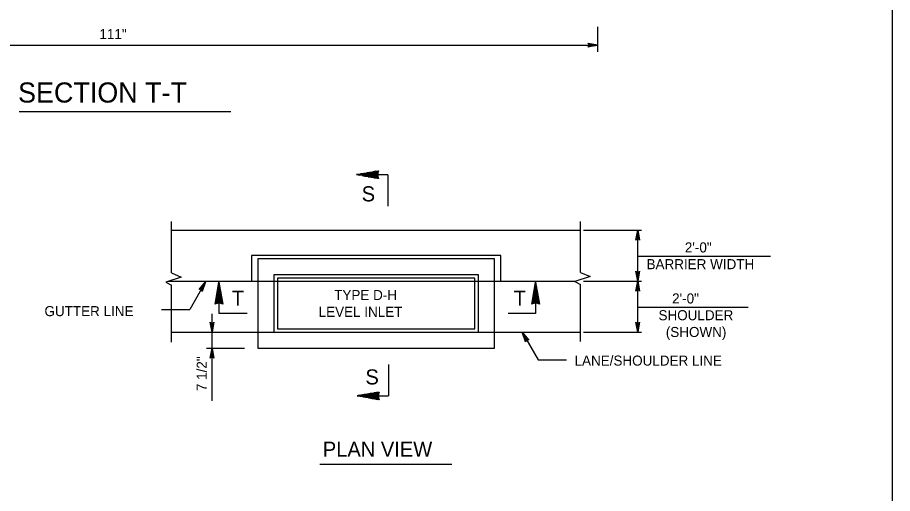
# Model space of a CAD drawing. Extents: x 2087776 to 2104538, y 970919 to 982612.
# Drawn here: x 2095145 to 2096001, y 979635 to 980101 of the extents above; entities that cross this region are included whole.
import ezdxf

# ---------------------------------------------------------------- set-up
doc = ezdxf.new("R2010")
doc.units = 0
doc.layers.add('1', color=7, linetype='Continuous')

msp = doc.modelspace()

# ---------------------------------------------------------------- linework, layer by layer
at = {"layer": '1'}
for p, q in [((2095712.65, 980067.42), (2095712.65, 980091.85)), ((2094787.65, 980073.9), (2095712.65, 980073.9)), ((2095146.59, 980009.06), (2095353.51, 980009.06)), ((2095497.32, 979947.29), (2095507.2, 979947.29)), ((2095507.28, 979947.24), (2095507.28, 979916.58)), ((2095295.77, 979851.22), (2095295.77, 979901.31)), ((2095695.77, 979851.66), (2095695.77, 979901.31)), ((2095295.77, 979893.06), (2095695.77, 979893.06)), ((2095698.46, 979893.06), (2095755.26, 979893.06)), ((2095751.62, 979843.06), (2095751.62, 979893.06)), ((2095617.64, 979868.06), (2095373.89, 979868.06)), ((2095373.89, 979868.06), (2095373.89, 979843.06)), ((2095611.39, 979864.94), (2095380.14, 979864.94)), ((2095380.14, 979864.94), (2095380.14, 979843.06)), ((2095611.39, 979843.06), (2095611.39, 979864.94)), ((2095617.64, 979843.06), (2095617.64, 979868.06)), ((2095751.62, 979867.66), (2095881.41, 979867.66)), ((2095595.77, 979849.31), (2095395.77, 979849.31)), ((2095395.77, 979849.31), (2095395.77, 979843.06)), ((2095592.38, 979845.93), (2095399.15, 979845.93)), ((2095399.15, 979845.93), (2095399.15, 979843.06)), ((2095592.38, 979843.06), (2095592.38, 979845.93)), ((2095595.77, 979843.06), (2095595.77, 979849.31)), ((2095292.75, 979843.06), (2095691.46, 979843.06)), ((2095295.77, 979783.36), (2095295.77, 979839.18)), ((2095329.03, 979842.52), (2095313.53, 979815.44)), ((2095380.14, 979843.06), (2095380.14, 979777.44)), ((2095395.77, 979843.06), (2095395.77, 979793.06)), ((2095399.15, 979843.06), (2095399.15, 979796.45)), ((2095592.38, 979796.45), (2095592.38, 979843.06)), ((2095595.77, 979793.06), (2095595.77, 979843.06)), ((2095611.39, 979777.44), (2095611.39, 979843.06)), ((2095695.77, 979784.03), (2095695.77, 979839.7)), ((2095698.46, 979843.06), (2095755.26, 979843.06)), ((2095751.62, 979793.06), (2095751.62, 979843.06)), ((2095342.05, 979821.47), (2095342.05, 979811.59)), ((2095651.73, 979821.47), (2095651.73, 979811.59)), ((2095285.77, 979815.44), (2095313.53, 979815.44)), ((2095369.74, 979811.59), (2095342.05, 979811.59)), ((2095651.73, 979811.59), (2095625.02, 979811.59)), ((2095751.62, 979817.66), (2095859.62, 979817.66)), ((2095335.28, 979726.03), (2095335.28, 979811.26)), ((2095399.15, 979796.45), (2095592.38, 979796.45)), ((2095295.77, 979793.06), (2095695.77, 979793.06)), ((2095395.77, 979793.06), (2095595.77, 979793.06)), ((2095638.69, 979793.06), (2095654.19, 979765.97)), ((2095698.46, 979793.06), (2095755.26, 979793.06)), ((2095329.78, 979777.44), (2095367.13, 979777.44)), ((2095380.14, 979777.44), (2095611.39, 979777.44)), ((2095507.8, 979761.61), (2095507.8, 979730.95)), ((2095654.19, 979765.97), (2095681.96, 979765.97)), ((2095497.92, 979730.95), (2095507.8, 979730.95)), ((2095440.64, 979664.02), (2095569.91, 979664.02))]:
    msp.add_line(p, q, dxfattribs=at)
for points in [[(2096000.74, 978763.82), (2096000.74, 980614.22), (2093422, 980614.22), (2093422, 978763.82), (2096000.74, 978763.82), (2096000.74, 978850.3), (2095344.57, 978850.3), (2095344.57, 979062.5), (2096000.74, 979062.5), (2096000.74, 979157.53), (2095344.57, 979157.53), (2095344.57, 978763.82), (2095603.11, 978763.82), (2095603.11, 978850.3), (2095603.11, 978763.82), (2095855.73, 978763.82), (2095855.73, 978850.3), (2095855.73, 978809.9), (2096000.74, 978809.9)], [(2095712.65, 980073.9), (2095702.87, 980072.06), (2095703.24, 980072.32), (2095703.62, 980072.58), (2095703.81, 980072.91), (2095704.01, 980073.24), (2095704.07, 980073.57), (2095704.12, 980073.9), (2095704.07, 980074.22), (2095704.01, 980074.55), (2095703.81, 980074.88), (2095703.62, 980075.21), (2095703.24, 980075.47), (2095702.87, 980075.73), (2095712.65, 980073.9), (2095703.24, 980075.47), (2095703.62, 980075.21), (2095712.65, 980073.9), (2095703.81, 980074.88), (2095704.01, 980074.55), (2095712.65, 980073.9), (2095704.07, 980074.22), (2095704.12, 980073.9), (2095712.65, 980073.9), (2095704.07, 980073.57), (2095704.01, 980073.24), (2095712.65, 980073.9), (2095703.81, 980072.91), (2095703.62, 980072.58), (2095712.65, 980073.9), (2095703.24, 980072.32)], [(2095498.06, 979943.49), (2095476.56, 979947.29), (2095498.06, 979950.99), (2095497.82, 979950.5), (2095495.54, 979950.56), (2095492.76, 979950.08), (2095497.66, 979950.02), (2095497.57, 979949.52), (2095489.41, 979949.5), (2095486.52, 979949.01), (2095497.44, 979949.02), (2095497.32, 979948.48), (2095483.58, 979948.49), (2095480.31, 979947.93), (2095497.26, 979947.96), (2095497.29, 979947.47), (2095477.54, 979947.46), (2095476.6, 979947.28), (2095479.34, 979946.8), (2095497.23, 979946.93), (2095497.31, 979946.43), (2095482.09, 979946.31), (2095484.8, 979945.84), (2095497.4, 979945.84), (2095497.4, 979945.37), (2095487.87, 979945.29), (2095490.99, 979944.74), (2095497.57, 979944.79), (2095497.71, 979944.26), (2095493.55, 979944.29), (2095496.7, 979943.73), (2095497.9, 979943.85)], [(2095751.62, 979893.06), (2095753.46, 979883.27), (2095753.2, 979883.65), (2095752.93, 979884.03), (2095752.61, 979884.22), (2095752.28, 979884.42), (2095751.95, 979884.47), (2095751.62, 979884.53), (2095751.29, 979884.47), (2095750.97, 979884.42), (2095750.64, 979884.22), (2095750.31, 979884.03), (2095750.05, 979883.65), (2095749.79, 979883.27), (2095751.62, 979893.06), (2095750.05, 979883.65), (2095750.31, 979884.03), (2095751.62, 979893.06), (2095750.64, 979884.22), (2095750.97, 979884.42), (2095751.62, 979893.06), (2095751.29, 979884.47), (2095751.62, 979884.53), (2095751.62, 979893.06), (2095751.95, 979884.47), (2095752.28, 979884.42), (2095751.62, 979893.06), (2095752.61, 979884.22), (2095752.93, 979884.03), (2095751.62, 979893.06), (2095753.2, 979883.65)], [(2095295.77, 979851.22), (2095305.03, 979847.15), (2095290.13, 979842.19), (2095295.77, 979839.18)], [(2095695.77, 979851.66), (2095705.09, 979847.61), (2095690.2, 979842.64), (2095695.77, 979839.7)], [(2095751.62, 979843.06), (2095749.79, 979852.85), (2095750.05, 979852.47), (2095750.31, 979852.09), (2095750.64, 979851.9), (2095750.97, 979851.7), (2095751.29, 979851.65), (2095751.62, 979851.59), (2095751.95, 979851.65), (2095752.28, 979851.7), (2095752.61, 979851.9), (2095752.93, 979852.09), (2095753.2, 979852.47), (2095753.46, 979852.85), (2095751.62, 979843.06), (2095753.2, 979852.47), (2095752.93, 979852.09), (2095751.62, 979843.06), (2095752.61, 979851.9), (2095752.28, 979851.7), (2095751.62, 979843.06), (2095751.95, 979851.65), (2095751.62, 979851.59), (2095751.62, 979843.06), (2095751.29, 979851.65), (2095750.97, 979851.7), (2095751.62, 979843.06), (2095750.64, 979851.9), (2095750.31, 979852.09), (2095751.62, 979843.06), (2095750.05, 979852.47)], [(2095329.03, 979842.52), (2095325.76, 979833.12), (2095325.72, 979833.58), (2095325.68, 979834.03), (2095325.5, 979834.37), (2095325.31, 979834.7), (2095325.05, 979834.91), (2095324.79, 979835.12), (2095324.48, 979835.23), (2095324.17, 979835.35), (2095323.79, 979835.34), (2095323.41, 979835.34), (2095322.99, 979835.14), (2095322.58, 979834.94), (2095329.03, 979842.52), (2095322.99, 979835.14), (2095323.41, 979835.34), (2095329.03, 979842.52), (2095323.79, 979835.34), (2095324.17, 979835.35), (2095329.03, 979842.52), (2095324.48, 979835.23), (2095324.79, 979835.12), (2095329.03, 979842.52), (2095325.05, 979834.91), (2095325.31, 979834.7), (2095329.03, 979842.52), (2095325.5, 979834.37), (2095325.68, 979834.03), (2095329.03, 979842.52), (2095325.72, 979833.58)], [(2095338.26, 979820.73), (2095342.05, 979842.23), (2095345.75, 979820.73), (2095345.27, 979820.97), (2095345.32, 979823.24), (2095344.84, 979826.03), (2095344.78, 979821.12), (2095344.29, 979821.22), (2095344.26, 979829.37), (2095343.77, 979832.26), (2095343.79, 979821.35), (2095343.25, 979821.46), (2095343.27, 979835.2), (2095342.7, 979838.48), (2095342.72, 979821.52), (2095342.24, 979821.49), (2095342.22, 979841.24), (2095342.05, 979842.2), (2095341.57, 979839.44), (2095341.69, 979821.56), (2095341.2, 979821.48), (2095341.08, 979836.69), (2095340.6, 979833.99), (2095340.6, 979821.39), (2095340.14, 979821.39), (2095340.06, 979830.91), (2095339.51, 979827.81), (2095339.56, 979821.22), (2095339.02, 979821.08), (2095339.05, 979825.24), (2095338.5, 979822.09), (2095338.62, 979820.88)], [(2095647.93, 979820.73), (2095651.73, 979842.23), (2095655.43, 979820.73), (2095654.94, 979820.97), (2095654.99, 979823.24), (2095654.52, 979826.03), (2095654.46, 979821.12), (2095653.96, 979821.22), (2095653.94, 979829.37), (2095653.45, 979832.26), (2095653.46, 979821.35), (2095652.92, 979821.46), (2095652.94, 979835.2), (2095652.38, 979838.48), (2095652.39, 979821.52), (2095651.91, 979821.49), (2095651.9, 979841.24), (2095651.72, 979842.2), (2095651.24, 979839.44), (2095651.37, 979821.56), (2095650.87, 979821.48), (2095650.76, 979836.69), (2095650.28, 979833.99), (2095650.28, 979821.39), (2095649.81, 979821.39), (2095649.73, 979830.91), (2095649.18, 979827.81), (2095649.23, 979821.22), (2095648.69, 979821.08), (2095648.73, 979825.24), (2095648.18, 979822.09), (2095648.29, 979820.88)], [(2095751.62, 979843.06), (2095753.46, 979833.27), (2095753.2, 979833.65), (2095752.93, 979834.03), (2095752.61, 979834.22), (2095752.28, 979834.42), (2095751.95, 979834.47), (2095751.62, 979834.53), (2095751.29, 979834.47), (2095750.97, 979834.42), (2095750.64, 979834.22), (2095750.31, 979834.03), (2095750.05, 979833.65), (2095749.79, 979833.27), (2095751.62, 979843.06), (2095750.05, 979833.65), (2095750.31, 979834.03), (2095751.62, 979843.06), (2095750.64, 979834.22), (2095750.97, 979834.42), (2095751.62, 979843.06), (2095751.29, 979834.47), (2095751.62, 979834.53), (2095751.62, 979843.06), (2095751.95, 979834.47), (2095752.28, 979834.42), (2095751.62, 979843.06), (2095752.61, 979834.22), (2095752.93, 979834.03), (2095751.62, 979843.06), (2095753.2, 979833.65)], [(2095335.28, 979793.06), (2095333.44, 979802.85), (2095333.7, 979802.47), (2095333.96, 979802.09), (2095334.29, 979801.9), (2095334.62, 979801.7), (2095334.95, 979801.65), (2095335.28, 979801.59), (2095335.6, 979801.65), (2095335.93, 979801.7), (2095336.26, 979801.9), (2095336.59, 979802.09), (2095336.85, 979802.47), (2095337.11, 979802.85), (2095335.28, 979793.06), (2095336.85, 979802.47), (2095336.59, 979802.09), (2095335.28, 979793.06), (2095336.26, 979801.9), (2095335.93, 979801.7), (2095335.28, 979793.06), (2095335.6, 979801.65), (2095335.28, 979801.59), (2095335.28, 979793.06), (2095334.95, 979801.65), (2095334.62, 979801.7), (2095335.28, 979793.06), (2095334.29, 979801.9), (2095333.96, 979802.09), (2095335.28, 979793.06), (2095333.7, 979802.47)], [(2095751.62, 979793.06), (2095749.79, 979802.85), (2095750.05, 979802.47), (2095750.31, 979802.09), (2095750.64, 979801.9), (2095750.97, 979801.7), (2095751.29, 979801.65), (2095751.62, 979801.59), (2095751.95, 979801.65), (2095752.28, 979801.7), (2095752.61, 979801.9), (2095752.93, 979802.09), (2095753.2, 979802.47), (2095753.46, 979802.85), (2095751.62, 979793.06), (2095753.2, 979802.47), (2095752.93, 979802.09), (2095751.62, 979793.06), (2095752.61, 979801.9), (2095752.28, 979801.7), (2095751.62, 979793.06), (2095751.95, 979801.65), (2095751.62, 979801.59), (2095751.62, 979793.06), (2095751.29, 979801.65), (2095750.97, 979801.7), (2095751.62, 979793.06), (2095750.64, 979801.9), (2095750.31, 979802.09), (2095751.62, 979793.06), (2095750.05, 979802.47)], [(2095638.69, 979793.06), (2095645.15, 979785.48), (2095644.73, 979785.68), (2095644.32, 979785.87), (2095643.94, 979785.88), (2095643.56, 979785.88), (2095643.24, 979785.77), (2095642.93, 979785.66), (2095642.67, 979785.44), (2095642.42, 979785.23), (2095642.23, 979784.9), (2095642.04, 979784.57), (2095642, 979784.11), (2095641.96, 979783.66), (2095638.69, 979793.06), (2095642, 979784.11), (2095642.04, 979784.57), (2095638.69, 979793.06), (2095642.23, 979784.9), (2095642.42, 979785.23), (2095638.69, 979793.06), (2095642.67, 979785.44), (2095642.93, 979785.66), (2095638.69, 979793.06), (2095643.24, 979785.77), (2095643.56, 979785.88), (2095638.69, 979793.06), (2095643.94, 979785.88), (2095644.32, 979785.87), (2095638.69, 979793.06), (2095644.73, 979785.68)], [(2095335.28, 979777.44), (2095337.11, 979767.65), (2095336.85, 979768.03), (2095336.59, 979768.4), (2095336.26, 979768.6), (2095335.93, 979768.79), (2095335.6, 979768.85), (2095335.28, 979768.91), (2095334.95, 979768.85), (2095334.62, 979768.79), (2095334.29, 979768.6), (2095333.96, 979768.4), (2095333.7, 979768.03), (2095333.44, 979767.65), (2095335.28, 979777.44), (2095333.7, 979768.03), (2095333.96, 979768.4), (2095335.28, 979777.44), (2095334.29, 979768.6), (2095334.62, 979768.79), (2095335.28, 979777.44), (2095334.95, 979768.85), (2095335.28, 979768.91), (2095335.28, 979777.44), (2095335.6, 979768.85), (2095335.93, 979768.79), (2095335.28, 979777.44), (2095336.26, 979768.6), (2095336.59, 979768.4), (2095335.28, 979777.44), (2095336.85, 979768.03)], [(2095498.66, 979727.15), (2095477.15, 979730.95), (2095498.66, 979734.65), (2095498.41, 979734.16), (2095496.14, 979734.22), (2095493.35, 979733.73), (2095498.26, 979733.68), (2095498.16, 979733.18), (2095490.01, 979733.16), (2095487.12, 979732.66), (2095498.03, 979732.68), (2095497.92, 979732.14), (2095484.18, 979732.15), (2095480.91, 979731.59), (2095497.86, 979731.61), (2095497.89, 979731.13), (2095478.14, 979731.12), (2095477.19, 979730.94), (2095479.94, 979730.46), (2095497.83, 979730.59), (2095497.91, 979730.09), (2095482.68, 979729.97), (2095485.4, 979729.49), (2095497.99, 979729.49), (2095498, 979729.03), (2095488.47, 979728.94), (2095491.58, 979728.4), (2095498.16, 979728.45), (2095498.31, 979727.91), (2095494.15, 979727.95), (2095497.3, 979727.39), (2095498.5, 979727.51)]]:
    msp.add_lwpolyline(points, dxfattribs=at)
for centre, start, end in [((2095507.28, 979947.24), 157.87619, 202.12381), ((2095342.01, 979811.51), 67.87619, 112.12381), ((2095651.69, 979811.51), 67.87619, 112.12381), ((2095507.88, 979730.9), 157.87619, 202.12381)]:
    msp.add_arc(centre, 9.95, start, end, dxfattribs=at)

# ---------------------------------------------------------------- texts
for s, height, p in [('111"', 9.843, (2095225.14, 980079.87)), ('SECTION T-T', 19.685, (2095145.56, 980017.77)), ('S', 14.76, (2095481.59, 979921.11)), ('2\'-0"', 9.843, (2095797.65, 979871.19)), ('BARRIER WIDTH', 9.8425, (2095760.22, 979854.78)), ('T', 14.76, (2095354.53, 979818.97)), ('TYPE D-H', 9.843, (2095454.75, 979824.58)), ('T', 14.76, (2095630.2, 979819.15)), ('2\'-0"', 9.843, (2095785.2, 979821.26)), ('GUTTER LINE', 9.8425, (2095171.4, 979808.86)), ('LEVEL INLET', 9.8425, (2095439.52, 979808.18)), ('SHOULDER', 9.843, (2095771.9, 979804.86)), ('(SHOWN)', 9.843, (2095779.07, 979788.45)), ('LANE/SHOULDER LINE', 9.8425, (2095689.8, 979760.46)), ('S', 14.76, (2095485.25, 979742.03)), ('PLAN VIEW', 14.69, (2095443.61, 979671.35))]:
    msp.add_text(s, height=height, dxfattribs=at).set_placement(p)
msp.add_text('7 1/2"', height=9.843, rotation=90, dxfattribs=at).set_placement((2095330.14, 979735.56))

doc.saveas('drawing.dxf')
